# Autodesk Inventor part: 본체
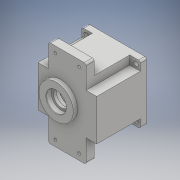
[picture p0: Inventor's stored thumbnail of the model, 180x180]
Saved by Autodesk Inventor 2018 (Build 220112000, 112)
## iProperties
Created: 2020-07
Part Number: 본체
Material: 일반
Document SubType Name: Modeling
Designer: Admin
Density: 1 g/cm^3
Appearance: 기본값
Author: Admin
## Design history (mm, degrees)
sketch "스케치1"
  geometry: L1 (-30, 70)-(30, 70); L2 (30, 70)-(30, -70); L3 (30, -70)-(-30, -70); L4 (-30, -70)-(-30, 70); L5 (-30, 70)-(30, -70); L6 (30, 70)-(-30, -70); 1 further point
  constraints: 12 end point, 2 midpoint, 2 parallel, 1 horizontal, 1 perpendicular
  dimensions: "d0" = 140 distance of L1.end L2.end; "d1" = 60 distance between parallel lines of L4 L2
extrude "돌출1" new body sketch "스케치1" distance "d2" = 13; taper "d3" = 0 deg
sketch "스케치2"
  geometry: L1 (-47, 47)-(47, 47); L2 (47, 47)-(47, -47); L3 (47, -47)-(-47, -47); L4 (-47, -47)-(-47, 47); L5 (-47, 47)-(47, -47); L6 (47, 47)-(-47, -47); 1 further point
  constraints: 12 end point, 2 midpoint, 2 parallel, 1 horizontal, 1 perpendicular
  dimensions: "d4" = 94 distance of L1.end L2.end; "d5" = 94 distance of L2.end L3.end
extrude "돌출2" join sketch "스케치2" distance "d6" = 80; taper "d7" = 0 deg
sketch "스케치3"
  geometry: L1 (-30, 33)-(30, 33); L2 (30, 33)-(30, -33); L3 (30, -33)-(-30, -33); L4 (-30, -33)-(-30, 33); L5 (-30, 33)-(30, -33); L6 (30, 33)-(-30, -33); L7 (47, 47)-(47, -47) reference; L8 (30, -33)-(47, -33); L9 (47, -33)-(47, -47); L10 (47, -47)-(30, -47); L11 (30, -47)-(30, -33); L12 (30, 33)-(47, 33); L13 (47, 33)-(47, 47); L14 (47, 47)-(30, 47); L15 (30, 47)-(30, 33); L16 (-47, 47)-(-30, 47) reference; L17 (-30, 33)-(-47, 33); L18 (-47, 33)-(-47, 47); L19 (-47, 47)-(-30, 47); L20 (-30, 47)-(-30, 33); L21 (-47, -47)-(-47, 47) reference; L22 (-30, -33)-(-47, -33); L23 (-47, -33)-(-47, -47); L24 (-47, -47)-(-30, -47); L25 (-30, -47)-(-30, -33); 1 further point
  constraints: 44 end point, 10 parallel, 5 horizontal, 5 perpendicular, 2 midpoint
  dimensions: "d8" = 66 distance of L1.end L2.end; "d9" = 60 distance of L2.end L3.end
extrude "돌출3" cut sketch "스케치3" distance "d10" = 70; taper "d11" = 0 deg
sketch "스케치4"
  geometry: C1 r 43 at (0, 0); 1 further point
  constraints: 1 centre point, 1 coincident
  dimensions: "d12" = 86 diameter of C1
extrude "돌출4" cut sketch "스케치4" distance "d13" = 9; taper "d14" = 0 deg
sketch "스케치5"
  geometry: C1 r 40 at (0, 0); 1 further point
  constraints: 1 centre point, 1 coincident
  dimensions: "d15" = 80 diameter of C1
extrude "돌출5" cut sketch "스케치5" distance "d16" = 62; taper "d17" = 0 deg
sketch "스케치6"
  geometry: L1 (0, -40)-(0, 40); L2 (-40, 0)-(40, 0); L3 (-11, -40)-(-11, 40); L4 (20, -40)-(20, 40); A1 r 40 centre (0, 0) between (0, -40) and (0, 40) reference; A2 r 21 centre (-11, 0) between (6.119, 12.163) and (6.119, -12.163); A3 r 15 centre (20, 0) between (10.47, -11.584) and (10.47, 11.584); A4 r 3 centre (8.565, -13.901) between (10.47, -11.584) and (6.119, -12.163); A5 r 3 centre (8.565, 13.901) between (6.119, 12.163) and (10.47, 11.584); 3 further points
  constraints: 12 point on circle, 8 end point, 6 midpoint, 4 centre point, 3 symmetric about line, 2 parallel, 2 point on line, 2 tangent, 1 horizontal, 1 vertical, 1 other
  dimensions: "d18" = 11 distance between parallel lines of L1 L3; "d19" = 20 distance between parallel lines of L1 L4; "d20" = 42 diameter of A2; "d21" = 30 diameter of A3; "d22" = 6 diameter of A4
extrude "돌출6" join sketch "스케치6" distance "d23" = 7; taper "d24" = 0 deg
sketch "스케치7"
  geometry: C1 r 17.5 at (-11, 0); A1 r 21 centre (-11, 0) between (6.119, 12.163) and (6.119, -12.163) reference; 1 further point
  constraints: 1 centre point, 1 coincident
  dimensions: "d25" = 35 diameter of C1
extrude "돌출7" cut sketch "스케치7" distance "d26" = 10; taper "d27" = 0 deg
sketch "스케치8"
  geometry: C1 r 27.5 at (-11, 0); A1 r 21 centre (-11, 0) between (6.119, 12.163) and (6.119, -12.163) reference; 1 further point
  constraints: 1 centre point, 1 coincident
  dimensions: "d28" = 55 diameter of C1
extrude "돌출8" join sketch "스케치8" distance "d29" = 7; taper "d30" = 0 deg
sketch "스케치9"
  geometry: C1 r 27.5 at (0, 0) reference; C2 r 16 at (0, 0); 1 further point
  constraints: 1 centre point, 1 coincident
  dimensions: "d31" = 32 diameter of C2
extrude "돌출9" cut sketch "스케치9" distance "d32" = 8.3; taper "d33" = 0 deg
sketch "스케치10"
  geometry: C1 r 27.5 at (0, 0) reference; C2 r 12.5 at (0, 0); 1 further point
  constraints: 1 centre point, 1 coincident
  dimensions: "d34" = 25 diameter of C2
extrude "돌출10" cut sketch "스케치10" extent not by distance; stored distance "d35" = 8.3; taper "d36" = 0 deg
sketch "스케치11"
  geometry: C1 r 11 at (20, 0); A1 r 15 centre (20, 0) between (10.47, -11.584) and (10.47, 11.584) reference; 1 further point
  constraints: 1 centre point, 1 coincident
  dimensions: "d37" = 22 diameter of C1
extrude "돌출11" cut sketch "스케치11" distance "d38" = 7; taper "d39" = 0 deg
sketch "스케치12"
  geometry: C1 r 11 at (0, 0) reference; C2 r 9.5 at (0, 0); 1 further point
  constraints: 1 centre point, 1 coincident
  dimensions: "d40" = 19 diameter of C2
extrude "돌출12" cut sketch "스케치12" distance "d41" = 3; taper "d42" = 0 deg
sketch "스케치13"
  geometry: L1 (40, 40)-(-40, 40); L2 (-40, 40)-(-40, -40); L3 (-40, -40)-(40, -40); L4 (40, -40)-(40, 40); L5 (40, 40)-(-40, -40); L6 (-40, 40)-(40, -40); C1 r 3.5 at (40, -40); C2 r 3.5 at (-40, -40); C3 r 3.5 at (-40, 40); C4 r 3.5 at (40, 40); 2 further points
  constraints: 12 end point, 5 coincident, 4 centre point, 2 midpoint, 2 parallel, 1 horizontal, 1 perpendicular
  dimensions: "d43" = 80 distance of L2.end L3.end; "d44" = 80 distance of L1.end L2.end; "d45" = 7 diameter of C1; "d46" = 7 diameter of C2; "d47" = 7 diameter of C3; "d48" = 7 diameter of C4
extrude "돌출13" cut sketch "스케치13" extent not by distance; stored distance "d49" = 3; taper "d50" = 0 deg
sketch "스케치14"
  geometry: L1 (19, -60)-(-19, -60); L2 (-19, -60)-(-19, 60); L3 (-19, 60)-(19, 60); L4 (19, 60)-(19, -60); L5 (19, -60)-(-19, 60); L6 (-19, -60)-(19, 60); 5 further points
  constraints: 12 end point, 4 coincident, 2 midpoint, 2 parallel, 1 horizontal, 1 perpendicular
  dimensions: "d51" = 120 distance of L1.end L2.end; "d52" = 38 distance of L1.start L1.end
hole "구멍1" sketch "스케치14" at (-19, -60), (19, -60), (-19, 60), (19, 60) diameter "d53" = 4.5; stored, may be unused: countersink angle "d57" = 90 deg, drill point angle "d59" = 0 deg; dims "d54" = 6, "d55" = 10, "d56" = 5, "d58" = 8
sketch "스케치15"
  geometry: L1 (0, -36)-(0, 36); L2 (-36, 0)-(36, 0); A1 r 36 centre (0, 0) between (0, -36) and (0, 36); A2 r 4 centre (0, -36) between (3.995, -36.19) and (-3.995, -36.19); A3 r 4 centre (0, 36) between (-3.995, 36.19) and (3.995, 36.19); A4 r 3 centre (-6.992, -36.333) between (-7.559, -39.279) and (-4.045, -35.772); A5 r 3 centre (6.992, -36.333) between (4.045, -35.772) and (7.559, -39.279); A6 r 3 centre (-6.992, 36.333) between (-4.045, 35.772) and (-7.559, 39.279); A7 r 3 centre (6.992, 36.333) between (7.559, 39.279) and (4.045, 35.772); A8 r 40 centre (0, 0) between (-7.559, -39.279) and (7.559, -39.279); A9 r 40 centre (0, 0) between (7.559, 39.279) and (-7.559, 39.279); 4 further points
  constraints: 25 point on circle, 9 centre point, 9 symmetric about line, 5 coincident, 4 end point, 4 midpoint, 1 horizontal, 1 tangent, 1 vertical, 6 other
  dimensions: "d60" = 72 diameter of A1; "d61" = 8 diameter of A2; "d62" = 8 diameter of A3; "d63" = 6 diameter of A4
extrude "돌출14" join sketch "스케치15" stored distance "d64" = 3; taper "d65" = 0 deg
sketch "스케치16"
  geometry: A1 r 4 centre (0, -36) between (3.995, -36.19) and (-3.995, -36.19) reference; A2 r 4 centre (0, 36) between (-3.995, 36.19) and (3.995, 36.19) reference; 3 further points
  constraints: 2 coincident
hole "구멍2" sketch "스케치16" at (0, -36), (0, 36) diameter "d66" = 3.242; stored, may be unused: countersink angle "d70" = 90 deg, drill point angle "d72" = 118 deg; dims "d67" = 7, "d68" = 10, "d69" = 5, "d71" = 9
chamfer "모따기1" distance "d73" = 0.8; stored, may be unused: second distance "d74" = 2, angle "d75" = 30 deg
fillet "모깎기1" dims "d76" = 3
chamfer "모따기2" distance "d77" = 1; stored, may be unused: second distance "d78" = 2, angle "d79" = 45 deg
chamfer "모따기3" distance "d80" = 1; stored, may be unused: second distance "d81" = 2, angle "d82" = 45 deg
fillet "모깎기2" dims "d83" = 3
fillet "모깎기3" dims "d84" = 3
sketch "스케치17"
  geometry: L1 (-11, 80)-(77, 80) reference; L2 (77, 80)-(-11, 80) reference; L3 (33, 0)-(33, 80); 2 further points
  constraints: 2 end point, 2 midpoint, 1 coincident, 1 other
  dimensions: "d90" = 40 distance from line of L1 point (33, 40)
feature "엠보싱1" sketch "스케치17" dims "d0" = 140, "d1" = 60, "d8" = 66, "d9" = 60, "d87" = 0.5, "d88" = 0
chamfer "모따기4" distance "d91" = 1; stored, may be unused: second distance "d92" = 2, angle "d93" = 45 deg
node "솔리드1"
